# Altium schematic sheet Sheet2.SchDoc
size A4; SheetNumber: 1; SheetTotal: 1
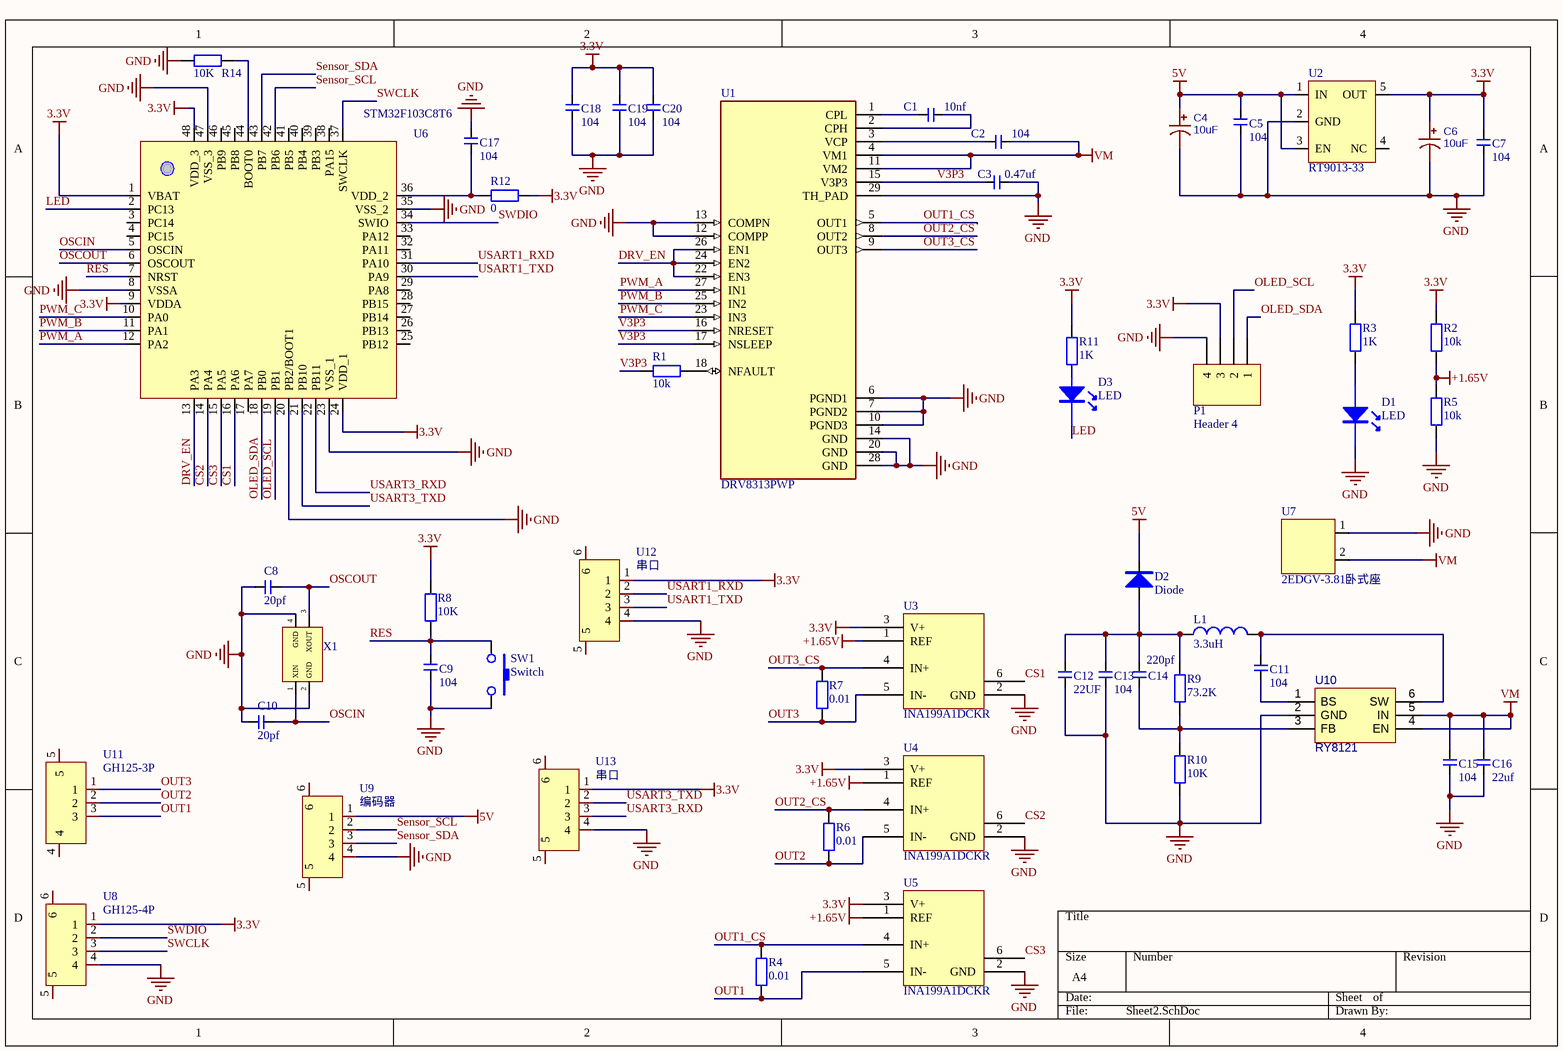
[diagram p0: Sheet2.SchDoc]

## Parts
C1  10nf  [C0603]
C2  104  [C0603]
C3  0.47uf  [C0603]
C4  10uF  [CD A(3216)]
C5  104  [C0603]
C6  10uF  [CD A(3216)]
C7  104  [C0603]
C8  20pf  [C0603]
C9  104  [C0603]
C10  20pf  [C0603]
C11  104  [C0402]
C12  22UF  [C0402]
C13  104  [C0402]
C14  220pf  [C0402]
C15  104  [C0402]
C16  22uf  [C0402]
C17  104  [C0603]
C18  104  [C0603]
C19  104  [C0603]
C20  104  [C0603]
D1  LED  [LED0402]
D2  Diode  [ESC_L1.2-W0.8-LS1.6-RD]
D3  LED  [LED0402]
L1  3.3uH  [0402 TPC 4*4*2]
P1  Header 4  [HDR1X4]
R1  10k  [R0603]
R2  10k  [R0603]
R3  1K  [R0402]
R4  0.01  [R1206]
R5  10k  [R0603]
R6  0.01  [R1206]
R7  0.01  [R1206]
R8  10K  [R0603]
R9  73.2K  [R0603]
R10  10K  [R0603]
R11  1K  [R0402]
R12  0  [R0603]
R14  10K  [R0603]
SW1  Switch  [SW-SMD_L3.9-W3.6-LS4.8-EH]
U1  DRV8313PWP  [HTSSOP-28]
U2  RT9013-33  [SOT-23-5_L2.9-W1.6-P0.95-LS2.8-BR]
U3  INA199A1DCKR  [SOT363]
U4  INA199A1DCKR  [SOT363]
U5  INA199A1DCKR  [SOT363]
U6  STM32F103C8T6  [48P]
U7  2EDGV-3.81卧式座  [2EDGV-3.81卧式座]
U8  GH125-4P  [CONN-SMD_4P-P1.27_GH125-S04DCA-00]
U9  编码器  [CONN-SMD_4P-P1.27_GH125-S04DCA-00]
U10  RY8121  [SOT-23-6]
U11  GH125-3P  [CONN-SMD_3P-P1.27_JS_GH125-S03CCA-00]
U12  串口  [CONN-SMD_4P-P1.27_GH125-S04DCA-00]
U13  串口  [CONN-SMD_4P-P1.27_GH125-S04DCA-00]
X1  XTAL-4  [OSC-SMD_4P-L3.2-W2.5-BL]  (value not drawn)

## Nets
3.3V: C6.1 C7.2 C18.1 C19.1 C20.1 P1.3 R2.2 R3.1 R8.2 R11.1 R12.2 U2.5(OUT) U3.3(V+) U4.3(V+) U5.3(V+) U6.1(VBAT) U6.9(VDDA) U6.24(VDD_1) U6.48(VDD_3) U8.1 U12.1 U13.1
5V: C4.1 C5.2 D2.1 U2.1(IN) U2.3(EN) U9.1
+1.65V: R2.1 R5.2 U3.1(REF) U4.1(REF) U5.1(REF)
GND: C3.2 C4.2 C5.1 C6.2 C7.1 C8.1 C9.2 C10.1 C12.1 C13.1 C15.1 C16.1 C17.1 C18.2 C19.2 C20.2 D1.N P1.4 R5.1 R10.1 R14.1 SW1.2 U1.6(PGND1) U1.7(PGND2) U1.10(PGND3) U1.12(COMPP) U1.13(COMPN) U1.14(GND) U1.20(GND) U1.28(GND) U1.29(TH_PAD) U2.2(GND) U3.2(GND) U4.2(GND) U5.2(GND) U6.8(VSSA) U6.20(PB2/BOOT1) U6.23(VSS_1) U6.35(VSS_2) U6.47(VSS_3) U7.1 U8.4 U9.4 U10.2(GND) U12.4 U13.4 X1.2(GND) X1.4(GND)
VM: C2.1 C15.2 C16.2 U1.4(VM1) U1.11(VM2) U7.2 U10.4(EN) U10.5(IN)
CS1: U3.6 U6.16(PA6)
CS2: U4.6 U6.14(PA4)
CS3: U5.6 U6.15(PA5)
DRV_EN: U1.22(EN3) U1.24(EN2) U1.26(EN1) U6.13(PA3)
LED: D3.N U6.2(PC13)
OLED_SCL: P1.2 U6.19(PB1)
OLED_SDA: P1.1 U6.18(PB0)
OSCIN: C10.2 U6.5(OSCIN) X1.1(XIN)
OSCOUT: C8.2 U6.6(OSCOUT) X1.3(XOUT)
OUT1: R4.1 U5.5(IN-) U11.3
OUT1_CS: R4.2 U1.5(OUT1) U5.4(IN+)
OUT2: R6.1 U4.5(IN-) U11.2
OUT2_CS: R6.2 U1.8(OUT2) U4.4(IN+)
OUT3: R7.1 U3.5(IN-) U11.1
OUT3_CS: R7.2 U1.9(OUT3) U3.4(IN+)
PWM_A: U1.27(IN1) U6.12(PA2)
PWM_B: U1.25(IN2) U6.11(PA1)
PWM_C: U1.23(IN3) U6.10(PA0)
RES: C9.1 R8.1 SW1.1 U6.7(NRST)
Sensor_SCL: U6.42(PB6) U9.2
Sensor_SDA: U6.43(PB7) U9.3
SWCLK: U6.37(SWCLK) U8.3
SWDIO: U6.34(SWIO) U8.2
USART1_RXD: U6.31(PA10) U12.2
USART1_TXD: U6.30(PA9) U12.3
USART3_RXD: U6.22(PB11) U13.3
USART3_TXD: U6.21(PB10) U13.2
V3P3: C3.1 R1.1 U1.15(V3P3) U1.16(NRESET) U1.17(NSLEEP)
NetC1_1: C1.1 U1.2(CPH)
NetC1_2: C1.2 U1.1(CPL)
NetC2_2: C2.2 U1.3(VCP)
NetC11_1: C11.1 U10.1(BS)
NetC11_2: C11.2 L1.2 U10.6(SW)
NetC12_2: C12.2 C13.2 C14.2 D2.2 L1.1 R9.2
NetC14_1: C14.1 R9.1 R10.2 U10.3(FB)
NetC17_2: C17.2 R12.1 U6.36(VDD_2)
NetD1_A: D1.A R3.2
NetD3_A: D3.A R11.2
NetR1_2: R1.2 U1.18(NFAULT)
NetR14_2: R14.2 U6.44(BOOT0)

Not connected (* = marked no-connect by the designer): U2 4(NC); U6 3(PC14) 4(PC15) 17(PA7) 25(PB12) 26(PB13) 27(PB14) 28(PB15) 29(PA8) 32(PA11) 33(PA12) 38(PA15) 39(PB3) 40(PB4) 41(PB5) 45(PB8) 46(PB9); U8 5 6; U9 5 6; U11 4 5; U12 5 6; U13 5 6

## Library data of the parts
C1-C3 C5 C7-C20 = C: 无极性电容; BOM名称: 无极性贴片电容; 版权归属: 源创客
C4 C6 = CAP+: 电解电容 10uf  贴片型 钽电容的正极是实物有线的一段; BOM_Manufacturer: ROQANG; BOM_Manufacturer Part: RVT1V100M0405; nameAlias: Capacitance
D2 = 二极管: Diode 1N series
L1 = L: 电感; BOM名称: 小功率贴片电感; 版权归属: 源创客
P1 = Header 4: Header, 4-Pin
R1-R12 R14 = R: 电阻; BOM名称: 贴片电阻; 版权归属: 源创客
U1 = DRV8313PWP: 65-V max, 3-A peak 3-phase motor driver 28-HTSSOP -40 to 125; MF: Texas Instruments
U2 = RT9013-33: 3.3V降压 500mA 最大输入5.5V
U9 U12 U13 = GH125-4P
U10 = RY8121: 18V 2A 1MHz Synchronous Step-Down Regulator
X1 = XTAL-4: 贴片晶振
